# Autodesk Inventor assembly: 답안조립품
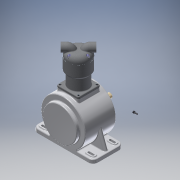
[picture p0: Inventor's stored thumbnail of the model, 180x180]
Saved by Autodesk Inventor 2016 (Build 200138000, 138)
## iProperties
Created: 2015-06
Part Number: 답안조립품
Document SubType Name: Assembly
Designer: Administrator
Author: Administrator
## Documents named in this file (15)
- C:\Users\Administrator\Desktop\450606V1010\답안조립품.iam
- C:\Users\Administrator\Desktop\450606V1010\본체.ipt
- C:\Users\Administrator\Desktop\450606V1010\베어링 6204.ipt
- C:\Users\Administrator\Desktop\450606V1010\메인커버.ipt
- C:\Users\Administrator\Desktop\450606V1010\메인 크랭크 축-구동부.ipt
- C:\Users\Administrator\Desktop\450606V1010\크랭크 서브축.ipt
- C:\Users\Administrator\Desktop\450606V1010\베어링 NA 4902.ipt
- C:\Users\Administrator\Desktop\450606V1010\커넥팅 로드.ipt
- C:\Users\Administrator\Desktop\450606V1010\피스톤 핀.ipt
- C:\Users\Administrator\Desktop\450606V1010\피스톤.ipt
- C:\Users\Administrator\Desktop\450606V1010\실린더.ipt
- C:\Users\Administrator\Desktop\450606V1010\실린더헤드.ipt
- C:\Users\Administrator\Desktop\450606V1010\오일실.ipt
- C:\Users\Administrator\Desktop\450606V1010\M5x0.8.ipt
- C:\Users\Administrator\Desktop\450606V1010\M4x0.7.ipt
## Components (11 placed, 4 different names)
1. 피스톤 핀:1
2. 피스톤:1
3. M4x0.7:1
4. M4x0.7:2
5. M4x0.7:3
6. M4x0.7:4
7. M4x0.7:5
8. M5x0.8:1
9. M5x0.8:2
10. M5x0.8:3
11. M5x0.8:4
